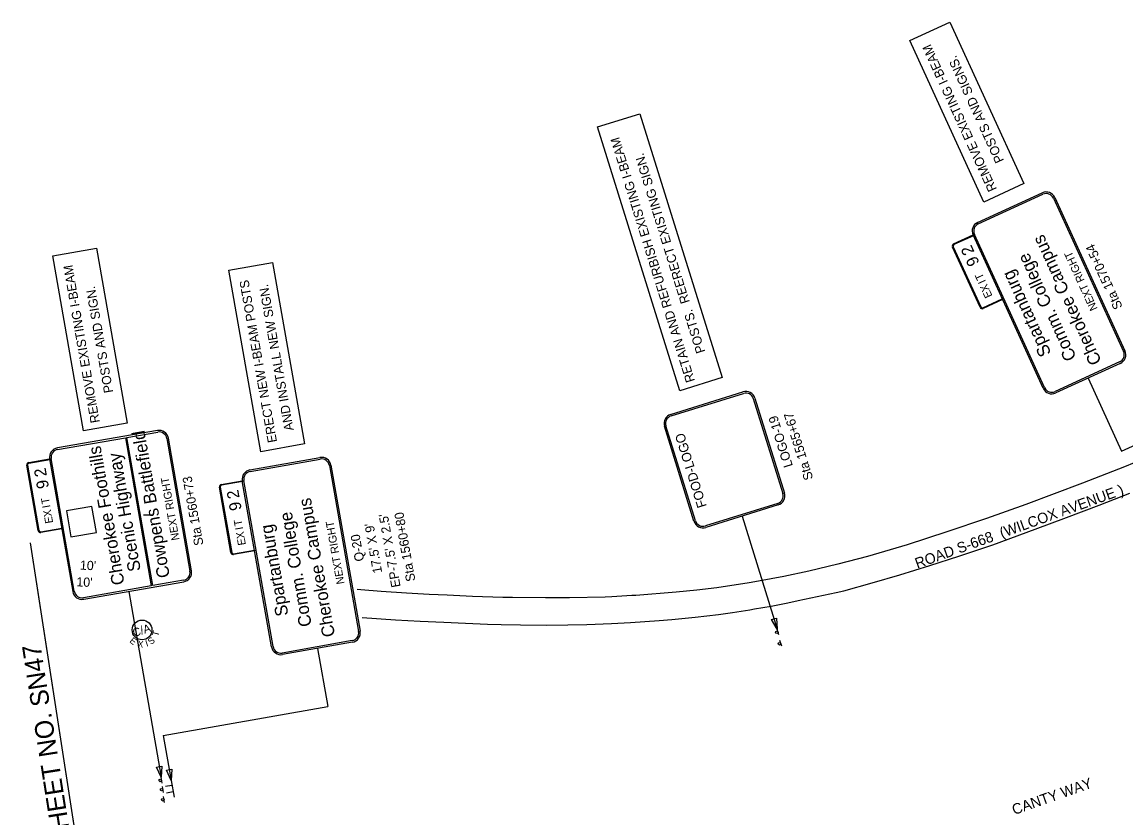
# Model space of a CAD drawing. Extents: x 1803351 to 1804929, y 1187729 to 1188936.
# Drawn here: x 1803351 to 1804190, y 1188078 to 1188683 of the extents above; entities that cross this region are included whole.
import ezdxf

# ---------------------------------------------------------------- set-up
doc = ezdxf.new("R2010")
doc.units = 0
for name, color, linetype in [('GIS ROW', 7, 'Continuous'), ('RD_EX_DV_Prop', 7, 'Continuous'), ('RD_EX_RW', 7, 'Continuous'), ('RD_PD_Final_TX', 7, 'Continuous'), ('RD_SHT_MatchLine', 7, 'Continuous'), ('RD_TX_RoadID', 7, 'Continuous'), ('Survey Property', 7, 'Continuous')]:
    doc.layers.add(name, color=color, linetype=linetype)

msp = doc.modelspace()

# ---------------------------------------------------------------- linework, layer by layer
at = {"layer": 'GIS ROW'}
msp.add_circle((1803442.34, 1188220.84), 7.5, dxfattribs=at)
at = {"layer": 'RD_EX_RW'}
for points in [[(1804204.02, 1188350.81), (1804189.13, 1188344.8), (1804157.19, 1188332.43), (1804114.17, 1188316.09), (1804084.41, 1188305.64), (1804054.29, 1188295.37), (1804024.1, 1188285.56), (1803993.95, 1188276.72), (1803971.19, 1188270.87), (1803949.25, 1188265.62), (1803930.21, 1188261.57), (1803911.09, 1188257.9), (1803903.99, 1188256.64), (1803879.21, 1188252.91), (1803864.07, 1188251.17), (1803848.32, 1188249.57), (1803817.76, 1188247.14), (1803814.73, 1188246.92), (1803799.46, 1188246.06), (1803794.31, 1188245.85), (1803767.18, 1188245.3), (1803749.07, 1188245.15), (1803723.98, 1188245.42), (1803716.54, 1188245.57), (1803693.66, 1188246.28), (1803674.28, 1188247.2), (1803660.58, 1188247.79), (1803643.33, 1188248.68), (1803624.2, 1188250.08), (1803608.56, 1188251.29), (1803605.93, 1188251.51)], [(1803609.6, 1188230.37), (1803609.76, 1188230.36), (1803634.95, 1188228.57), (1803653.72, 1188227.47), (1803671.71, 1188226.69), (1803688.15, 1188225.88), (1803704.9, 1188225.29), (1803715.35, 1188224.9), (1803730.04, 1188224.66), (1803749.54, 1188224.6), (1803766, 1188224.68), (1803780.5, 1188225.1), (1803799.11, 1188225.82), (1803813.78, 1188226.57), (1803835.5, 1188228.07), (1803845.15, 1188228.87), (1803862.92, 1188230.59), (1803880.64, 1188232.71), (1803891.17, 1188234.15), (1803904.39, 1188236.24), (1803907.98, 1188236.85), (1803920.6, 1188238.9), (1803933.16, 1188241.35), (1803941.06, 1188243.1), (1803969.96, 1188249.4), (1803975.88, 1188250.64), (1803997.43, 1188256.55), (1804018.5, 1188262.73), (1804041.28, 1188269.75), (1804063.35, 1188276.94), (1804089.05, 1188285.62), (1804121.21, 1188297.38), (1804145.14, 1188306.26), (1804169.94, 1188315.6), (1804193.25, 1188324.71)]]:
    msp.add_lwpolyline(points, dxfattribs=at)
at = {"layer": 'RD_SHT_MatchLine'}
for p, q in [((1803357.33, 1188286.92), (1803443.72, 1187728.78)), ((1803359.07, 1188275.71), (1803438.45, 1187762.8))]:
    msp.add_line(p, q, dxfattribs=at)
at = {"layer": 'Survey Property'}
for p, q in [((1804025.98, 1188668.71), (1804056.54, 1188682.71)), ((1804056.54, 1188682.71), (1804112.75, 1188559.95)), ((1804082.19, 1188545.95), (1804025.98, 1188668.71)), ((1803788.7, 1188603.12), (1803820.8, 1188613.12)), ((1803820.8, 1188613.12), (1803883.24, 1188412.59)), ((1803851.14, 1188402.6), (1803788.7, 1188603.12)), ((1804112.75, 1188559.95), (1804082.19, 1188545.95)), ((1803374.6, 1188505.21), (1803407.72, 1188510.98)), ((1803397.79, 1188372.2), (1803374.6, 1188505.21)), ((1803407.72, 1188510.98), (1803430.91, 1188377.97)), ((1803508.39, 1188494.21), (1803541.49, 1188500.04)), ((1803541.49, 1188500.04), (1803565.8, 1188362.15)), ((1803532.7, 1188356.31), (1803508.39, 1188494.21)), ((1804186.95, 1188356.57), (1804350.61, 1188431.51)), ((1803883.24, 1188412.59), (1803851.14, 1188402.6)), ((1804161.5, 1188412.15), (1804186.95, 1188356.57)), ((1803430.91, 1188377.97), (1803397.79, 1188372.2)), ((1803429.65, 1188366.94), (1803449.29, 1188254.32)), ((1803450.47, 1188254.53), (1803430.84, 1188367.15)), ((1803565.8, 1188362.15), (1803532.7, 1188356.31)), ((1803404.18, 1188314.63), (1803384.78, 1188311.25)), ((1803407.61, 1188294.93), (1803404.18, 1188314.63)), ((1803443.47, 1188308.37), (1803450.43, 1188308.29)), ((1803898.44, 1188307.27), (1803925.15, 1188221.47)), ((1803388.22, 1188291.55), (1803407.61, 1188294.93)), ((1803449.29, 1188254.32), (1803397.76, 1188245.34)), ((1803397.97, 1188244.16), (1803474.07, 1188257.42)), ((1803473.86, 1188258.61), (1803450.47, 1188254.53)), ((1803432.15, 1188250.12), (1803456.77, 1188108.93)), ((1803926.49, 1188217.17), (1803925.15, 1188221.47)), ((1803928.6, 1188208.52), (1803927.26, 1188212.82)), ((1803575.7, 1188206.84), (1803583.49, 1188162.66)), ((1803458.34, 1188140.6), (1803583.49, 1188162.66)), ((1803458.34, 1188140.6), (1803464.34, 1188106.54)), ((1803457.54, 1188104.5), (1803456.77, 1188108.93)), ((1803465.02, 1188102.69), (1803460.11, 1188101.82)), ((1803464.34, 1188106.54), (1803466.61, 1188093.7)), ((1803458.58, 1188097.43), (1803457.8, 1188101.86)), ((1803459.5, 1188089.81), (1803458.73, 1188094.25)), ((1803465.89, 1188097.75), (1803460.98, 1188096.88))]:
    msp.add_line(p, q, dxfattribs=at)
for points in [[(1804077.61, 1188530.49), (1804126.71, 1188552.97)], [(1804078.11, 1188529.39), (1804127.21, 1188551.88)], [(1804135.16, 1188548.92), (1804188.5, 1188432.44)], [(1804136.26, 1188549.42), (1804189.59, 1188432.94)], [(1804059.34, 1188514.2), (1804074.07, 1188520.94), (1804074.32, 1188520.4)], [(1804074.32, 1188520.4), (1804059.59, 1188513.65)], [(1804127.4, 1188404.46), (1804074.07, 1188520.94)], [(1804128.49, 1188404.96), (1804075.16, 1188521.44)], [(1804079.43, 1188465.99), (1804058.45, 1188511.81)], [(1804058.99, 1188512.06), (1804079.98, 1188466.24)], [(1804081.57, 1188465.64), (1804096.3, 1188472.39), (1804096.55, 1188471.84), (1804081.82, 1188465.1)], [(1804185.55, 1188424.48), (1804136.45, 1188402)], [(1804186.04, 1188423.39), (1804136.95, 1188400.91)], [(1803844.18, 1188384.63), (1803899.17, 1188401.76)], [(1803844.54, 1188383.49), (1803899.53, 1188400.61)], [(1803907.04, 1188396.67), (1803929.52, 1188324.49)], [(1803908.19, 1188397.02), (1803930.67, 1188324.84)], [(1803454.02, 1188372.41), (1803377.92, 1188359.14)], [(1803430.84, 1188367.15), (1803454.23, 1188371.23)], [(1803861.92, 1188303.44), (1803839.45, 1188375.62)], [(1803863.07, 1188303.79), (1803840.59, 1188375.97)], [(1803378.13, 1188357.96), (1803429.65, 1188366.94)], [(1803461.17, 1188366.35), (1803478.74, 1188265.55)], [(1803479.92, 1188265.75), (1803462.35, 1188366.55)], [(1803363.3, 1188296.3), (1803354.64, 1188345.95)], [(1803355.23, 1188346.05), (1803363.89, 1188296.4)], [(1803356.11, 1188348.03), (1803372.07, 1188350.81), (1803372.17, 1188350.22)], [(1803372.17, 1188350.22), (1803356.21, 1188347.44)], [(1803372.07, 1188350.81), (1803389.64, 1188250.01)], [(1803390.82, 1188250.22), (1803373.25, 1188351.02)], [(1803524.37, 1188342.5), (1803577.55, 1188351.88)], [(1803524.58, 1188341.32), (1803577.76, 1188350.69)], [(1803584.71, 1188345.83), (1803606.95, 1188219.66)], [(1803585.89, 1188346.03), (1803608.13, 1188219.87)], [(1803509.86, 1188279.63), (1803501.11, 1188329.26)], [(1803501.71, 1188329.37), (1803510.46, 1188279.73)], [(1803502.57, 1188331.35), (1803518.53, 1188334.16), (1803518.63, 1188333.57)], [(1803518.63, 1188333.57), (1803502.68, 1188330.76)], [(1803540.77, 1188207.99), (1803518.53, 1188334.16)], [(1803541.95, 1188208.2), (1803519.71, 1188334.37)], [(1803925.58, 1188316.97), (1803870.58, 1188299.85)], [(1803925.93, 1188315.83), (1803870.94, 1188298.7)], [(1803384.78, 1188311.25), (1803388.22, 1188291.55)], [(1803365.28, 1188295.42), (1803381.24, 1188298.21), (1803381.34, 1188297.61), (1803365.38, 1188294.83)], [(1803511.85, 1188278.76), (1803527.8, 1188281.57), (1803527.9, 1188280.98), (1803511.95, 1188278.17)], [(1803602.08, 1188212.71), (1803548.9, 1188203.33)], [(1803602.29, 1188211.53), (1803549.11, 1188202.15)]]:
    msp.add_lwpolyline(points, dxfattribs=at)
for points in [[(1803924.67, 1188229.91), (1803925.15, 1188221.47), (1803920.76, 1188228.69)], [(1803457.28, 1188117.37), (1803456.77, 1188108.93), (1803453.25, 1188116.62)], [(1803464.94, 1188114.97), (1803464.34, 1188106.54), (1803460.9, 1188114.26)]]:
    msp.add_lwpolyline(points, close=True, dxfattribs=at)
for centre in [(1803924.85, 1188219.03), (1803926.96, 1188210.38), (1803456.16, 1188106.55), (1803457.19, 1188099.48), (1803458.12, 1188091.87)]:
    msp.add_circle(centre, 1, dxfattribs=at)
for centre, radius, start, end in [((1804129.71, 1188546.42), 7.2, 24.60317, 114.60317), ((1804129.71, 1188546.42), 6, 24.60317, 114.60317), ((1804080.61, 1188523.94), 7.2, 114.60317, 204.60317), ((1804080.61, 1188523.94), 6, 114.60317, 204.60317), ((1804060.09, 1188512.56), 1.8, 114.60317, 204.60317), ((1804060.09, 1188512.56), 1.2, 114.60317, 204.60317), ((1804081.07, 1188466.74), 1.8, 204.60317, 294.60317), ((1804081.07, 1188466.74), 1.2, 204.60317, 294.60317), ((1804183.05, 1188429.94), 6, 294.60317, 24.60317), ((1804183.05, 1188429.94), 7.2, 294.60317, 24.60317), ((1804133.95, 1188407.46), 7.2, 204.60317, 294.60317), ((1804133.95, 1188407.46), 6, 204.60317, 294.60317), ((1803901.32, 1188394.88), 7.2, 17.29655, 107.29655), ((1803901.32, 1188394.88), 6, 17.29655, 107.29655), ((1803846.32, 1188377.76), 7.2, 107.29655, 197.29655), ((1803846.32, 1188377.76), 6, 107.29655, 197.29655), ((1803455.26, 1188365.32), 7.2, 9.88969, 99.88969), ((1803455.26, 1188365.32), 6, 9.88969, 99.88969), ((1803379.16, 1188352.05), 7.2, 99.88969, 189.88969), ((1803379.16, 1188352.05), 6, 99.88969, 189.88969), ((1803356.42, 1188346.26), 1.8, 99.88969, 189.88969), ((1803356.42, 1188346.26), 1.2, 99.88969, 189.88969), ((1803578.8, 1188344.78), 7.2, 9.99793, 99.99793), ((1803578.8, 1188344.78), 6, 9.99793, 99.99793), ((1803525.62, 1188335.41), 7.2, 99.99793, 189.99793), ((1803525.62, 1188335.41), 6, 99.99793, 189.99793), ((1803502.89, 1188329.57), 1.8, 99.99793, 189.99793), ((1803502.89, 1188329.57), 1.2, 99.99793, 189.99793), ((1803923.79, 1188322.7), 6, 287.29655, 17.29655), ((1803923.79, 1188322.7), 7.2, 287.29655, 17.29655), ((1803868.8, 1188305.58), 7.2, 197.29655, 287.29655), ((1803868.8, 1188305.58), 6, 197.29655, 287.29655), ((1803365.07, 1188296.61), 1.8, 189.88969, 279.88969), ((1803365.07, 1188296.61), 1.2, 189.88969, 279.88969), ((1803511.64, 1188279.94), 1.8, 189.99793, 279.99793), ((1803511.64, 1188279.94), 1.2, 189.99793, 279.99793), ((1803472.83, 1188264.52), 6, 279.88969, 9.88969), ((1803472.83, 1188264.52), 7.2, 279.88969, 9.88969), ((1803396.73, 1188251.25), 7.2, 189.88969, 279.88969), ((1803396.73, 1188251.25), 6, 189.88969, 279.88969), ((1803601.04, 1188218.62), 6, 279.99793, 9.99793), ((1803601.04, 1188218.62), 7.2, 279.99793, 9.99793), ((1803547.86, 1188209.24), 7.2, 189.99793, 279.99793), ((1803547.86, 1188209.24), 6, 189.99793, 279.99793)]:
    msp.add_arc(centre, radius, start, end, dxfattribs=at)

# ---------------------------------------------------------------- texts
at = {"layer": 'GIS ROW'}
for s, height, rotation, p in [('C/A', 6.25, 17.67352, (1803436.28, 1188215.46)), ('T', 5, 75.85867, (1803454.7, 1188215.63)), ('E', 5, 320.88477, (1803432.38, 1188211.87)), ('X', 5, 353.31414, (1803438.65, 1188207.93)), ('I', 5, 17.47414, (1803445.74, 1188208.01)), ('S', 5, 39.46597, (1803449.16, 1188209.29))]:
    msp.add_text(s, height=height, rotation=rotation, dxfattribs=at).set_placement(p)
at = {"layer": 'RD_EX_DV_Prop'}
msp.add_text('MATCHLINE STA. 1560+00 SEE SHEET NO. SN47', height=14.1726, rotation=98.91974, dxfattribs=at).set_placement((1803433.14, 1187776.36))
at = {"layer": 'RD_PD_Final_TX'}
for p in [(1803395.01, 1188266.67), (1803392.3, 1188253.99)]:
    msp.add_text("10'", height=7, rotation=357.57398, dxfattribs=at).set_placement(p)
at = {"layer": 'RD_TX_RoadID'}
for s, rotation, p in [('ROAD S-668  (WILCOX AVENUE )', 19.79991, (1804031.68, 1188267.36)), ('CANTY WAY', 19.33813, (1804105.41, 1188080.19))]:
    msp.add_text(s, height=8, rotation=rotation, dxfattribs=at).set_placement(p)
at = {"layer": 'Survey Property'}
for s, height, rotation, p in [('REMOVE EXISTING I-BEAM', 6.9998, 114.60325, (1804092.36, 1188555.83)), ('POSTS AND SIGNS.', 6.9998, 114.60325, (1804097.83, 1188577.52)), ('RETAIN AND REFURBISH EXISTING I-BEAM', 7, 107.29663, (1803862.79, 1188410.15)), ('POSTS.  REERECT EXISTING SIGN.', 7, 107.29663, (1803870.56, 1188432.27)), ('2', 9, 114.60317, (1804075.39, 1188507.97)), ('Cherokee Campus', 9.6, 114.60317, (1804172.08, 1188424.73)), ('Sta 1570+54', 7, 114.60325, (1804187.94, 1188466.26)), ('Comm. College', 9.6, 114.60317, (1804152.96, 1188427.79)), ('NEXT RIGHT', 6, 114.60317, (1804168.93, 1188465.02)), ('REMOVE EXISTING I-BEAM', 6.9998, 99.88977, (1803410.22, 1188378.72)), ('9', 9, 114.60317, (1804079.18, 1188499.69)), ('T', 6, 114.60317, (1804082.75, 1188488.28)), ('Spartanburg', 9.6, 114.60317, (1804133.74, 1188431.06)), ('POSTS AND SIGN.', 6.9998, 99.88977, (1803420.45, 1188401.52)), ('ERECT NEW I-BEAM POSTS', 6.9998, 99.99801, (1803544.95, 1188363.79)), ('AND INSTALL NEW SIGN.', 6.9998, 99.99801, (1803557.57, 1188372.81)), ('I', 6, 114.60317, (1804084, 1188485.56)), ('X', 6, 114.60317, (1804086.83, 1188479.37)), ('E', 6, 114.60317, (1804088.98, 1188474.68)), ('LOGO-19', 7, 107.29663, (1803937.18, 1188345.55)), ('Sta 1565+67', 7, 107.29663, (1803952.65, 1188335.88)), ('Cowpens Battlefield', 9.6, 99.88969, (1803463.52, 1188261.23)), ('FOOD-LOGO', 7.2, 107.29655, (1803871.71, 1188314.93)), ('Cherokee Foothills', 9.6, 99.88969, (1803429.08, 1188255.79)), ('Scenic Highway', 9.6, 99.88969, (1803441.41, 1188266.08)), ('2', 9, 99.88969, (1803370.05, 1188337.93)), ('Sta 1560+73', 7, 99.88977, (1803489.03, 1188285.56)), ('9', 9, 99.88969, (1803371.61, 1188328.96)), ('NEXT RIGHT', 6, 99.88969, (1803470.76, 1188289.41)), ('T', 6, 99.88969, (1803372.17, 1188317.01)), ('2', 9, 99.99793, (1803516.54, 1188321.27)), ('Cherokee Campus', 9.6, 99.99793, (1803589.11, 1188216.34)), ('I', 6, 99.88969, (1803372.68, 1188314.07)), ('X', 6, 99.88969, (1803373.86, 1188307.36)), ('9', 9, 99.99793, (1803518.12, 1188312.31)), ('E', 6, 99.88969, (1803374.74, 1188302.28)), ('T', 6, 99.99793, (1803518.7, 1188300.36)), ('Comm. College', 9.6, 99.99793, (1803571.38, 1188224.12)), ("EP-7.5' X 2.5'", 7, 99.99801, (1803638.88, 1188253.78)), ('Sta 1560+80', 7, 99.99801, (1803650.17, 1188258.29)), ('I', 6, 99.99793, (1803519.22, 1188297.42)), ('X', 6, 99.99793, (1803520.4, 1188290.71)), ('Spartanburg', 9.6, 99.99793, (1803553.61, 1188232.13)), ('NEXT RIGHT', 6, 99.99793, (1803596.23, 1188256.12)), ("17.5' X 9'", 7, 99.99801, (1803624.9, 1188264.53)), ('E', 6, 99.99793, (1803521.29, 1188285.64)), ('Q-20', 7, 99.99801, (1803611.23, 1188273.54))]:
    msp.add_text(s, height=height, rotation=rotation, dxfattribs=at).set_placement(p)

doc.saveas('drawing.dxf')
